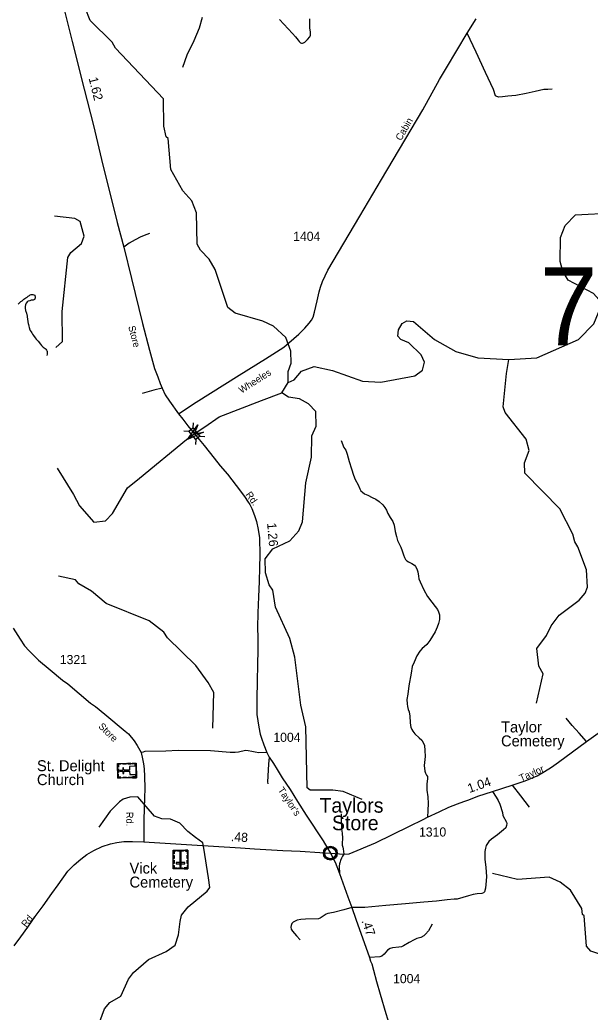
# Model space of a CAD drawing. Extents: x 2220236 to 2384410, y 720751 to 894131.
# Drawn here: x 2294988 to 2302795, y 851003 to 864576 of the extents above; entities that cross this region are included whole.
import ezdxf

# ---------------------------------------------------------------- set-up
doc = ezdxf.new("R2010")
doc.units = 0
doc.layers.add('Default', color=7, linetype='Continuous')

msp = doc.modelspace()

# ---------------------------------------------------------------- linework, layer by layer
at = {"layer": 'Default'}
for p, q in [((2298572, 859472), (2298662, 859617)), ((2297232, 858956), (2297301, 858951)), ((2297360, 859065), (2297354, 858996)), ((2297399, 858836), (2297394, 858767)), ((2297452, 858881), (2297521, 858875))]:
    msp.add_line(p, q, dxfattribs=at)
for points in [[(2295532, 864977), (2295702, 864281), (2295869, 863630), (2295994, 863130), (2296107, 862666), (2296318, 861802), (2296410, 861469), (2296514, 861039), (2296669, 860423), (2296763, 860058), (2296833, 859809), (2296875, 859691), (2296908, 859604), (2296936, 859537), (2296979, 859448), (2297036, 859358), (2297158, 859189)], [(2298662, 859617), (2298661, 859764), (2298701, 859881), (2298699, 860042), (2298630, 860233), (2298462, 860386), (2298312, 860453), (2297935, 860565), (2297835, 860640), (2297662, 861161), (2297578, 861302), (2297460, 861425), (2297417, 861509), (2297404, 861935), (2297344, 862100), (2297218, 862239), (2297055, 862531), (2297017, 862953), (2296992, 862978), (2296958, 863121), (2296954, 863495), (2296297, 864187), (2296253, 864270), (2295950, 864567), (2295882, 864741)], [(2297158, 859189), (2297400, 859348), (2297990, 859718), (2298352, 859939), (2298601, 860100), (2298805, 860278), (2298891, 860359), (2298948, 860426), (2298981, 860467), (2299001, 860511), (2299022, 860577), (2299056, 860732), (2299087, 860854), (2299104, 860918), (2299129, 860997), (2299204, 861150), (2299643, 861889), (2299938, 862392), (2300503, 863347), (2300732, 863761), (2300828, 863919), (2301111, 864394), (2301234, 864592)], [(2297219, 863927), (2297276, 864099), (2297375, 864293), (2297447, 864465), (2297489, 864613)], [(2298540, 864580), (2298718, 864391), (2298763, 864344), (2298797, 864299), (2298811, 864281), (2298821, 864269), (2298829, 864263), (2298844, 864258), (2298856, 864256), (2298870, 864261), (2298889, 864271), (2298904, 864283), (2298924, 864306), (2298958, 864344), (2298968, 864369), (2298968, 864407), (2298958, 864467), (2298957, 864505), (2298958, 864588)], [(2302274, 863630), (2302216, 863623), (2302162, 863623), (2302044, 863597), (2301917, 863570), (2301775, 863542), (2301669, 863532), (2301593, 863525), (2301545, 863520), (2301517, 863527), (2301501, 863539), (2301471, 863625), (2301364, 863854), (2301232, 864134), (2301111, 864394)], [(2301682, 859931), (2302065, 859953), (2302637, 860206), (2302843, 860418), (2302941, 860652), (2302914, 860753), (2302839, 860835), (2302495, 861015), (2302419, 861139), (2302384, 861273), (2302389, 861598), (2302454, 861764), (2302594, 861908), (2303118, 861936), (2303200, 862064), (2303256, 862263), (2303396, 862423), (2303628, 862600), (2303959, 862781), (2304000, 862845)], [(2295685, 861392), (2295834, 861516), (2295867, 861619), (2295813, 861817), (2295739, 861857), (2295462, 861892)], [(2296763, 861653), (2296728, 861641), (2296646, 861606), (2296568, 861569), (2296485, 861520), (2296410, 861469)], [(2295480, 860093), (2295572, 860176), (2295569, 860589), (2295644, 861325), (2295685, 861392)], [(2294964, 860686), (2294988, 860712), (2295002, 860722), (2295018, 860734), (2295030, 860744), (2295043, 860757), (2295068, 860772), (2295087, 860784), (2295103, 860795), (2295111, 860801), (2295119, 860807), (2295127, 860813), (2295141, 860819), (2295155, 860820), (2295167, 860818), (2295177, 860816), (2295191, 860812), (2295195, 860802), (2295197, 860793), (2295199, 860783), (2295199, 860780), (2295197, 860770), (2295195, 860764), (2295193, 860757), (2295188, 860753), (2295180, 860748), (2295169, 860743), (2295158, 860742), (2295144, 860740), (2295123, 860735), (2295102, 860729), (2295092, 860723), (2295086, 860717), (2295078, 860707), (2295074, 860701), (2295064, 860679), (2295059, 860655), (2295059, 860635), (2295061, 860625), (2295063, 860612), (2295067, 860599), (2295077, 860565), (2295086, 860523), (2295090, 860509), (2295094, 860485), (2295098, 860444), (2295102, 860423), (2295106, 860407), (2295111, 860387), (2295115, 860367), (2295125, 860335), (2295131, 860325), (2295141, 860307), (2295150, 860295), (2295160, 860279), (2295174, 860258), (2295198, 860228), (2295212, 860210), (2295239, 860180), (2295271, 860138), (2295284, 860123), (2295299, 860107), (2295308, 860099), (2295321, 860091), (2295335, 860081), (2295345, 860071), (2295354, 860059), (2295358, 860051), (2295362, 860045), (2295364, 860032), (2295362, 860014)], [(2298662, 859617), (2298745, 859650), (2298844, 859769), (2299018, 859835), (2299268, 859780), (2299678, 859636), (2299928, 859620), (2300394, 859707), (2300501, 859784), (2300525, 859893), (2300482, 859993), (2300314, 860157), (2300205, 860205), (2300163, 860249), (2300170, 860338), (2300219, 860422), (2300286, 860458), (2300377, 860449), (2300663, 860204), (2300956, 860039), (2301257, 859953), (2301682, 859931)], [(2295362, 860014), (2295360, 860003), (2295356, 859986)], [(2302058, 855230), (2302153, 855631), (2302094, 855737), (2302066, 855979), (2302198, 856155), (2302263, 856289), (2302370, 856431), (2302642, 856636), (2302725, 856734), (2302757, 856818), (2302746, 857054), (2302626, 857367), (2302584, 857434), (2302558, 857541), (2302379, 857889), (2301899, 858374), (2301897, 858519), (2301962, 858685), (2301919, 858841), (2301632, 859207), (2301606, 859281), (2301651, 859739), (2301682, 859931)], [(2296936, 859537), (2296823, 859509), (2296664, 859466)], [(2295497, 858444), (2295721, 858085), (2295806, 857928), (2296001, 857703), (2296159, 857722), (2296257, 857825), (2296462, 858174), (2296626, 858309), (2297269, 858834), (2297376, 858915), (2297522, 859007), (2297715, 859147), (2298298, 859369), (2298572, 859472)], [(2299673, 853911), (2299414, 854019), (2299272, 854039), (2298964, 854037), (2298922, 854071), (2298904, 854904), (2298835, 855203), (2298753, 855859), (2298683, 856116), (2298487, 856541), (2298451, 856773), (2298400, 856846), (2298349, 857014), (2298347, 857205), (2298453, 857340), (2298685, 857448), (2298809, 857585), (2298857, 857711), (2298902, 858245), (2298981, 858593), (2298986, 858885), (2299043, 859019), (2299041, 859219), (2298940, 859326), (2298814, 859393), (2298664, 859417), (2298572, 859472)], [(2297158, 859189), (2297219, 859115), (2297286, 859022), (2297444, 858834)], [(2297444, 858834), (2297511, 858754), (2297649, 858581), (2297730, 858476), (2297829, 858362), (2298010, 858131), (2298070, 858044), (2298105, 857991), (2298134, 857946), (2298164, 857890), (2298184, 857833), (2298203, 857784), (2298225, 857712), (2298250, 857604), (2298267, 857491), (2298275, 857254), (2298270, 857086), (2298262, 856893), (2298256, 856686), (2298244, 856463), (2298242, 856266), (2298247, 856123), (2298247, 855950), (2298243, 855761), (2298236, 855527), (2298232, 855292), (2298234, 855075), (2298257, 854902), (2298276, 854806), (2298295, 854749), (2298326, 854661), (2298367, 854555), (2298402, 854491), (2298459, 854406), (2298512, 854321), (2298579, 854208), (2298687, 854049), (2298788, 853882), (2298908, 853697), (2299138, 853348), (2299189, 853260), (2299239, 853177)], [(2299387, 858823), (2299423, 858725), (2299448, 858690), (2299468, 858637), (2299498, 858536), (2299528, 858433), (2299554, 858348), (2299578, 858287), (2299618, 858214), (2299641, 858159), (2299657, 858136), (2299676, 858114), (2299705, 858094), (2299750, 858073), (2299812, 858041), (2299861, 858018), (2299908, 857986), (2299958, 857940), (2299986, 857905), (2300006, 857870), (2300027, 857822), (2300059, 857767), (2300094, 857712), (2300110, 857666), (2300127, 857578), (2300142, 857510), (2300159, 857453), (2300178, 857407), (2300202, 857363), (2300223, 857315), (2300238, 857257), (2300253, 857221), (2300268, 857196), (2300285, 857177), (2300308, 857162), (2300353, 857138), (2300388, 857116), (2300404, 857099), (2300422, 857069), (2300434, 857026), (2300446, 856965), (2300451, 856928), (2300466, 856888), (2300519, 856779), (2300570, 856688), (2300627, 856613), (2300673, 856551), (2300703, 856510), (2300718, 856480), (2300731, 856438), (2300734, 856402), (2300732, 856374), (2300720, 856320), (2300700, 856269), (2300671, 856206), (2300636, 856144), (2300599, 856088), (2300558, 856033), (2300523, 856002), (2300496, 855978), (2300463, 855942), (2300423, 855875), (2300385, 855791), (2300359, 855729), (2300344, 855640), (2300314, 855467), (2300297, 855352), (2300287, 855279), (2300289, 855221), (2300294, 855183), (2300304, 855143), (2300319, 855110), (2300327, 855053), (2300332, 854967), (2300335, 854925), (2300340, 854901), (2300354, 854871), (2300367, 854844), (2300395, 854812), (2300453, 854756), (2300490, 854724), (2300508, 854693), (2300525, 854648), (2300533, 854580), (2300535, 854500), (2300523, 854376), (2300533, 854299), (2300539, 854271), (2300554, 854246), (2300566, 854226), (2300566, 854198), (2300559, 854120), (2300559, 854039), (2300574, 853947), (2300578, 853859), (2300571, 853760), (2300568, 853670)], [(2297630, 854888), (2297642, 855374), (2297565, 855512), (2297396, 855745), (2297009, 856123), (2296958, 856199), (2296756, 856355), (2296171, 856591), (2295969, 856763), (2295793, 856860), (2295751, 856918), (2295518, 856967)], [(2294898, 856255), (2294992, 856104), (2295052, 856015), (2295117, 855944), (2295190, 855873), (2295206, 855852), (2295243, 855816), (2295404, 855683), (2295573, 855545), (2295646, 855492), (2295957, 855228), (2296023, 855182), (2296152, 855079), (2296431, 854846), (2296475, 854811), (2296554, 854712), (2296595, 854650), (2296648, 854553)], [(2302746, 854706), (2302643, 854821), (2302550, 854922), (2302467, 855023)], [(2299239, 853177), (2299422, 853165), (2299495, 853170), (2299854, 853319), (2300322, 853545), (2300508, 853640), (2300568, 853670), (2300729, 853745), (2300858, 853806), (2300979, 853853), (2301067, 853886), (2301132, 853907), (2301256, 853956), (2301456, 854020), (2301726, 854108), (2301907, 854166), (2302069, 854235), (2302170, 854296), (2302265, 854356), (2302361, 854424), (2302746, 854706), (2303144, 854994)], [(2298367, 854555), (2298261, 854552), (2298207, 854557), (2298165, 854569), (2298115, 854578), (2298075, 854584), (2297981, 854561), (2297935, 854554), (2297865, 854556), (2297599, 854575), (2297157, 854580), (2296986, 854574), (2296698, 854569), (2296674, 854559), (2296648, 854553)], [(2296648, 854553), (2296669, 854466), (2296679, 854401), (2296688, 854329), (2296695, 854225), (2296697, 854068), (2296691, 853793), (2296684, 853625), (2296686, 853486), (2296685, 853334)], [(2298402, 854491), (2298391, 854397), (2298378, 854155), (2298382, 854126)], [(2301726, 854108), (2301842, 853961), (2301958, 853806)], [(2296018, 850700), (2296147, 851050), (2296221, 851135), (2296370, 851219), (2296476, 851454), (2296542, 851545), (2296748, 851724), (2296989, 851832), (2297112, 851919), (2297161, 852059), (2297184, 852244), (2297200, 852327), (2297290, 852445), (2297554, 852656), (2297587, 852707), (2297569, 852841), (2297508, 853245), (2297491, 853320), (2297393, 853393), (2297286, 853475), (2297178, 853586), (2297052, 853642), (2296933, 853648), (2296830, 853683), (2296604, 853946), (2296492, 853943), (2296400, 853915), (2296351, 853879), (2296225, 853753), (2296071, 853531)], [(2301456, 854020), (2301507, 853945), (2301537, 853896), (2301558, 853848), (2301593, 853732), (2301601, 853694), (2301650, 853601), (2301652, 853583), (2301651, 853555), (2301639, 853525), (2301609, 853496), (2301528, 853428), (2301443, 853369), (2301409, 853338), (2301372, 853282), (2301362, 853246), (2301355, 853202), (2301354, 853096), (2301365, 852982), (2301374, 852860), (2301373, 852798), (2301364, 852700), (2301347, 852650), (2301335, 852634), (2301311, 852624), (2301249, 852621), (2301191, 852610), (2301127, 852594), (2300976, 852550), (2300934, 852546), (2300838, 852541), (2300692, 852523), (2300520, 852509), (2300265, 852484), (2299997, 852462), (2299710, 852432), (2299530, 852436)], [(2299387, 853716), (2299388, 853630), (2299390, 853562), (2299393, 853507), (2299402, 853451), (2299405, 853381), (2299400, 853308), (2299402, 853285), (2299408, 853258), (2299415, 853235), (2299422, 853165)], [(2294912, 851910), (2295001, 852035), (2295096, 852164), (2295198, 852309), (2295305, 852458), (2295426, 852625), (2295512, 852744), (2295646, 852931), (2295731, 853016), (2295821, 853097), (2295905, 853157), (2296002, 853215), (2296115, 853268), (2296230, 853305), (2296315, 853323), (2296409, 853336), (2296532, 853339), (2296685, 853334)], [(2296685, 853334), (2297340, 853293), (2298006, 853251), (2298202, 853238), (2298589, 853216), (2298825, 853203), (2299096, 853187), (2299239, 853177)], [(2299239, 853177), (2299305, 853056), (2299363, 852897), (2299430, 852710), (2299478, 852582), (2299530, 852436), (2299588, 852273), (2299772, 851752), (2299789, 851700), (2299804, 851664), (2299830, 851579), (2299869, 851423), (2299920, 851248), (2299999, 850983), (2300042, 850837)], [(2299422, 853165), (2299403, 853137), (2299392, 853110), (2299379, 853077), (2299373, 853059), (2299364, 853030), (2299357, 852999), (2299363, 852897)], [(2305519, 850967), (2305241, 851238), (2305057, 851303), (2304533, 851258), (2304134, 851137), (2304026, 851136), (2303817, 851249), (2303698, 851398), (2303656, 851488), (2303338, 851603), (2303212, 851700), (2302802, 851837), (2302743, 851904), (2302714, 852320), (2302689, 852338), (2302680, 852420), (2302527, 852670), (2302384, 852782), (2302234, 852848), (2301801, 852817), (2301458, 852898)], [(2299530, 852436), (2299425, 852401), (2299283, 852364), (2299205, 852353), (2299183, 852343), (2299097, 852286), (2299076, 852280), (2298898, 852276), (2298832, 852269), (2298784, 852260), (2298756, 852248), (2298728, 852232), (2298710, 852214), (2298703, 852190), (2298699, 852164), (2298703, 852138), (2298719, 852112), (2298774, 852047), (2298827, 851993)], [(2300631, 852205), (2300580, 852116), (2300542, 852071), (2300519, 852046), (2300475, 852024), (2300424, 852008), (2300387, 851991), (2300316, 851955), (2300241, 851912), (2300210, 851897), (2300175, 851892), (2300091, 851881), (2300057, 851875), (2300021, 851850), (2299974, 851798), (2299944, 851770), (2299916, 851760), (2299772, 851752)]]:
    msp.add_lwpolyline(points, dxfattribs=at)
for points in [[(2297504, 858938), (2297282, 858838), (2297424, 859035), (2297376, 858915)], [(2297354, 858996), (2297452, 858881), (2297398, 858835), (2297301, 858951)], [(2296329, 854205), (2296324, 854404), (2296579, 854409), (2296583, 854210)], [(2296368, 854405), (2296368, 854394), (2296336, 854393), (2296337, 854352), (2296325, 854352), (2296324, 854404)], [(2296582, 854254), (2296580, 854366), (2296489, 854364), (2296490, 854313), (2296409, 854311), (2296408, 854344), (2296397, 854344), (2296398, 854311), (2296356, 854310), (2296356, 854298), (2296398, 854299), (2296399, 854266), (2296410, 854266), (2296409, 854300), (2296491, 854301), (2296492, 854252)], [(2296441, 854395), (2296398, 854394), (2296397, 854406), (2296441, 854407)], [(2296507, 854397), (2296464, 854396), (2296463, 854407), (2296507, 854408)], [(2296580, 854376), (2296568, 854376), (2296568, 854398), (2296527, 854397), (2296527, 854408), (2296579, 854409)], [(2296327, 854279), (2296326, 854331), (2296337, 854331), (2296338, 854279)], [(2296372, 854206), (2296372, 854217), (2296340, 854216), (2296339, 854257), (2296328, 854257), (2296329, 854205)], [(2296446, 854207), (2296403, 854206), (2296403, 854218), (2296446, 854219)], [(2296513, 854209), (2296470, 854208), (2296470, 854219), (2296513, 854220)], [(2296582, 854244), (2296571, 854243), (2296571, 854221), (2296531, 854220), (2296531, 854209), (2296583, 854210)], [(2299160, 853190), (2299161, 853195), (2299163, 853202), (2299166, 853209), (2299168, 853215), (2299172, 853221), (2299176, 853226), (2299180, 853230), (2299184, 853235), (2299190, 853239), (2299195, 853243), (2299200, 853246), (2299205, 853248), (2299210, 853251), (2299216, 853252), (2299220, 853254), (2299225, 853254), (2299229, 853255), (2299236, 853255), (2299240, 853255), (2299246, 853255), (2299251, 853254), (2299256, 853253), (2299261, 853252), (2299266, 853250), (2299273, 853247), (2299279, 853243), (2299284, 853240), (2299289, 853236), (2299292, 853233), (2299296, 853228), (2299300, 853224), (2299303, 853219), (2299307, 853214), (2299309, 853209), (2299311, 853204), (2299313, 853199), (2299314, 853194), (2299315, 853188), (2299316, 853183), (2299316, 853177), (2299316, 853172), (2299315, 853166), (2299314, 853161), (2299313, 853154), (2299311, 853149), (2299308, 853143), (2299305, 853137), (2299302, 853132), (2299298, 853127), (2299294, 853123), (2299289, 853118), (2299284, 853114), (2299279, 853110), (2299275, 853108), (2299268, 853104), (2299261, 853102), (2299255, 853100), (2299248, 853099), (2299244, 853098), (2299239, 853098), (2299234, 853098), (2299229, 853099), (2299224, 853099), (2299218, 853101), (2299213, 853102), (2299208, 853104), (2299203, 853106), (2299199, 853108), (2299193, 853112), (2299187, 853116), (2299182, 853121), (2299178, 853126), (2299175, 853130), (2299172, 853134), (2299167, 853141), (2299166, 853145), (2299164, 853149), (2299161, 853157), (2299160, 853164), (2299159, 853169), (2299159, 853175), (2299159, 853180), (2299159, 853186)], [(2297287, 852964), (2297088, 852964), (2297088, 853218), (2297287, 853218)], [(2297121, 853218), (2297121, 853207), (2297099, 853207), (2297099, 853167), (2297088, 853167), (2297088, 853218)], [(2297100, 853146), (2297100, 853103), (2297088, 853103), (2297088, 853146)], [(2297230, 853207), (2297145, 853207), (2297145, 853218), (2297230, 853218)], [(2297178, 852993), (2297197, 852993), (2297197, 853196), (2297178, 853196)], [(2297254, 853218), (2297254, 853207), (2297276, 853207), (2297276, 853167), (2297287, 853167), (2297287, 853218)], [(2297287, 853149), (2297287, 853105), (2297276, 853105), (2297276, 853149)], [(2297099, 853080), (2297099, 853037), (2297088, 853037), (2297088, 853080)], [(2297088, 853007), (2297099, 853007), (2297099, 852975), (2297140, 852975), (2297140, 852964), (2297088, 852964)], [(2297246, 853032), (2297246, 853051), (2297129, 853051), (2297129, 853032)], [(2297287, 853007), (2297276, 853007), (2297276, 852975), (2297235, 852975), (2297235, 852964), (2297287, 852964)], [(2297287, 853081), (2297287, 853038), (2297276, 853038), (2297276, 853081)], [(2297213, 852964), (2297161, 852964), (2297161, 852975), (2297213, 852975)]]:
    msp.add_lwpolyline(points, close=True, dxfattribs=at)
for centre, radius in [((2299238, 853177), 94.3), ((2299237, 853178), 76.7)]:
    msp.add_circle(centre, radius, dxfattribs=at)

# ---------------------------------------------------------------- texts
for s, height, rotation, p in [('1.62', 125, 284.0803, (2295928, 863778)), ('Cabin', 95, 59.7847, (2300205, 862915)), ('Store', 95, 284.4461, (2296471, 860381)), ('Wheeles', 95, 32.5254, (2298022, 859462)), ('Rd.', 95, 305.0634, (2298073, 858083)), ('1.26', 125, 275.058, (2298372, 857691)), ('Store', 95, 315.4771, (2296056, 854903)), ('Taylor', 95, 23.8658, (2301850, 854155)), ('1.04', 125, 19.1018, (2301142, 853999)), ("Taylor's", 95, 304.0792, (2298515, 854041)), ('Rd.', 95, 270.5725, (2296444, 853742)), ('.48', 125, 356.4303, (2297874, 853343)), ('Rd.', 95, 51.2153, (2295073, 852156)), ('.47', 125, 289.3761, (2299663, 852251))]:
    msp.add_text(s, height=height, rotation=rotation, dxfattribs=at).set_placement(p)
for s, height, p in [('1404', 125, (2298729, 861553)), ('76', 1066.3, (2302102, 860126)), ('1321', 125, (2295535, 855763)), ('Taylor', 150, (2301575, 854829)), ('1004', 125, (2298458, 854700)), ('Cemetery', 150, (2301575, 854638)), ('St. Delight', 150, (2295222, 854299)), ('Church', 150, (2295222, 854108)), ('Taylors', 200, (2299089, 853731)), ('Store', 200, (2299260, 853491)), ('1310', 125, (2300452, 853405)), ('Vick', 150, (2296489, 852898)), ('Cemetery', 150, (2296489, 852707)), ('1004', 125, (2300097, 851399))]:
    msp.add_text(s, height=height, dxfattribs=at).set_placement(p)

doc.saveas('drawing.dxf')
